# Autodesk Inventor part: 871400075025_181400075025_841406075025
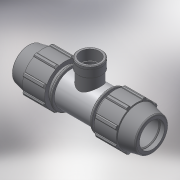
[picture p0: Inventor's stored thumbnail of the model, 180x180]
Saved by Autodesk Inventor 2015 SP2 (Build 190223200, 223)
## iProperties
Created: 2017-02
Part Number: 871400075025_181400075025_841406075025
Material: Generic
Description: PLASSON TEE WITH THREADED FEMALE OFFTAKE 75-2.1/2"-75
Document SubType Name: Modeling
Designer: KIM
Mass: 92.6774 g
Surface Area: 199.44 cm^2
Volume: 66.1981 cm^3
Density: 1 g/cm^3
Appearance: Default
Author: KIM
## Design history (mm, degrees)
derived "87140.ipt"
feature "Solid1::87140.ipt"
feature "Solid2::87140.ipt"
tag "TaggingFeature1"
body "Solid1"
other parameters: "d2" = 75, "d4" = 14.25, "d5" = 41.04, "d7" = 132, "d11" = 5.7, "d13" = 120 deg, "d14" = 97.5, "d15" = 12 deg, "d16" = 114.84, "d18" = 3.75, "d19" = 35 deg, "d20" = 17.5 deg, "d21" = 122.76, "d23" = 0, "d25" = 360 deg, "d27" = 2.64, "d33" = 1.5, "d42" = 61.56, "d43" = 3.96, "d46" = 2.25, "d68" = 10.26, "d72" = 85, "d76" = 72.226, "d80" = 2.16678, "d91" = 99, "d93" = 134, "d95" = 67.5, "d112" = 35, "d115" = 90.2825, "d116" = 135 deg, "d117" = 83.0599, "d118" = 342, "d119" = 67.5, "d121" = 0, "d122" = 67.5, "d124" = 0, "d128" = 0, "d129" = 7.5, "d130" = 10.5, "d131" = 0.3, "d132" = 0.3, "d133" = 90.2825, "d_" = 75, "E_" = 132, "A_" = 85, "l_" = 134, "l_2" = 35, "Rp_" = 72.226, "H_" = 342
